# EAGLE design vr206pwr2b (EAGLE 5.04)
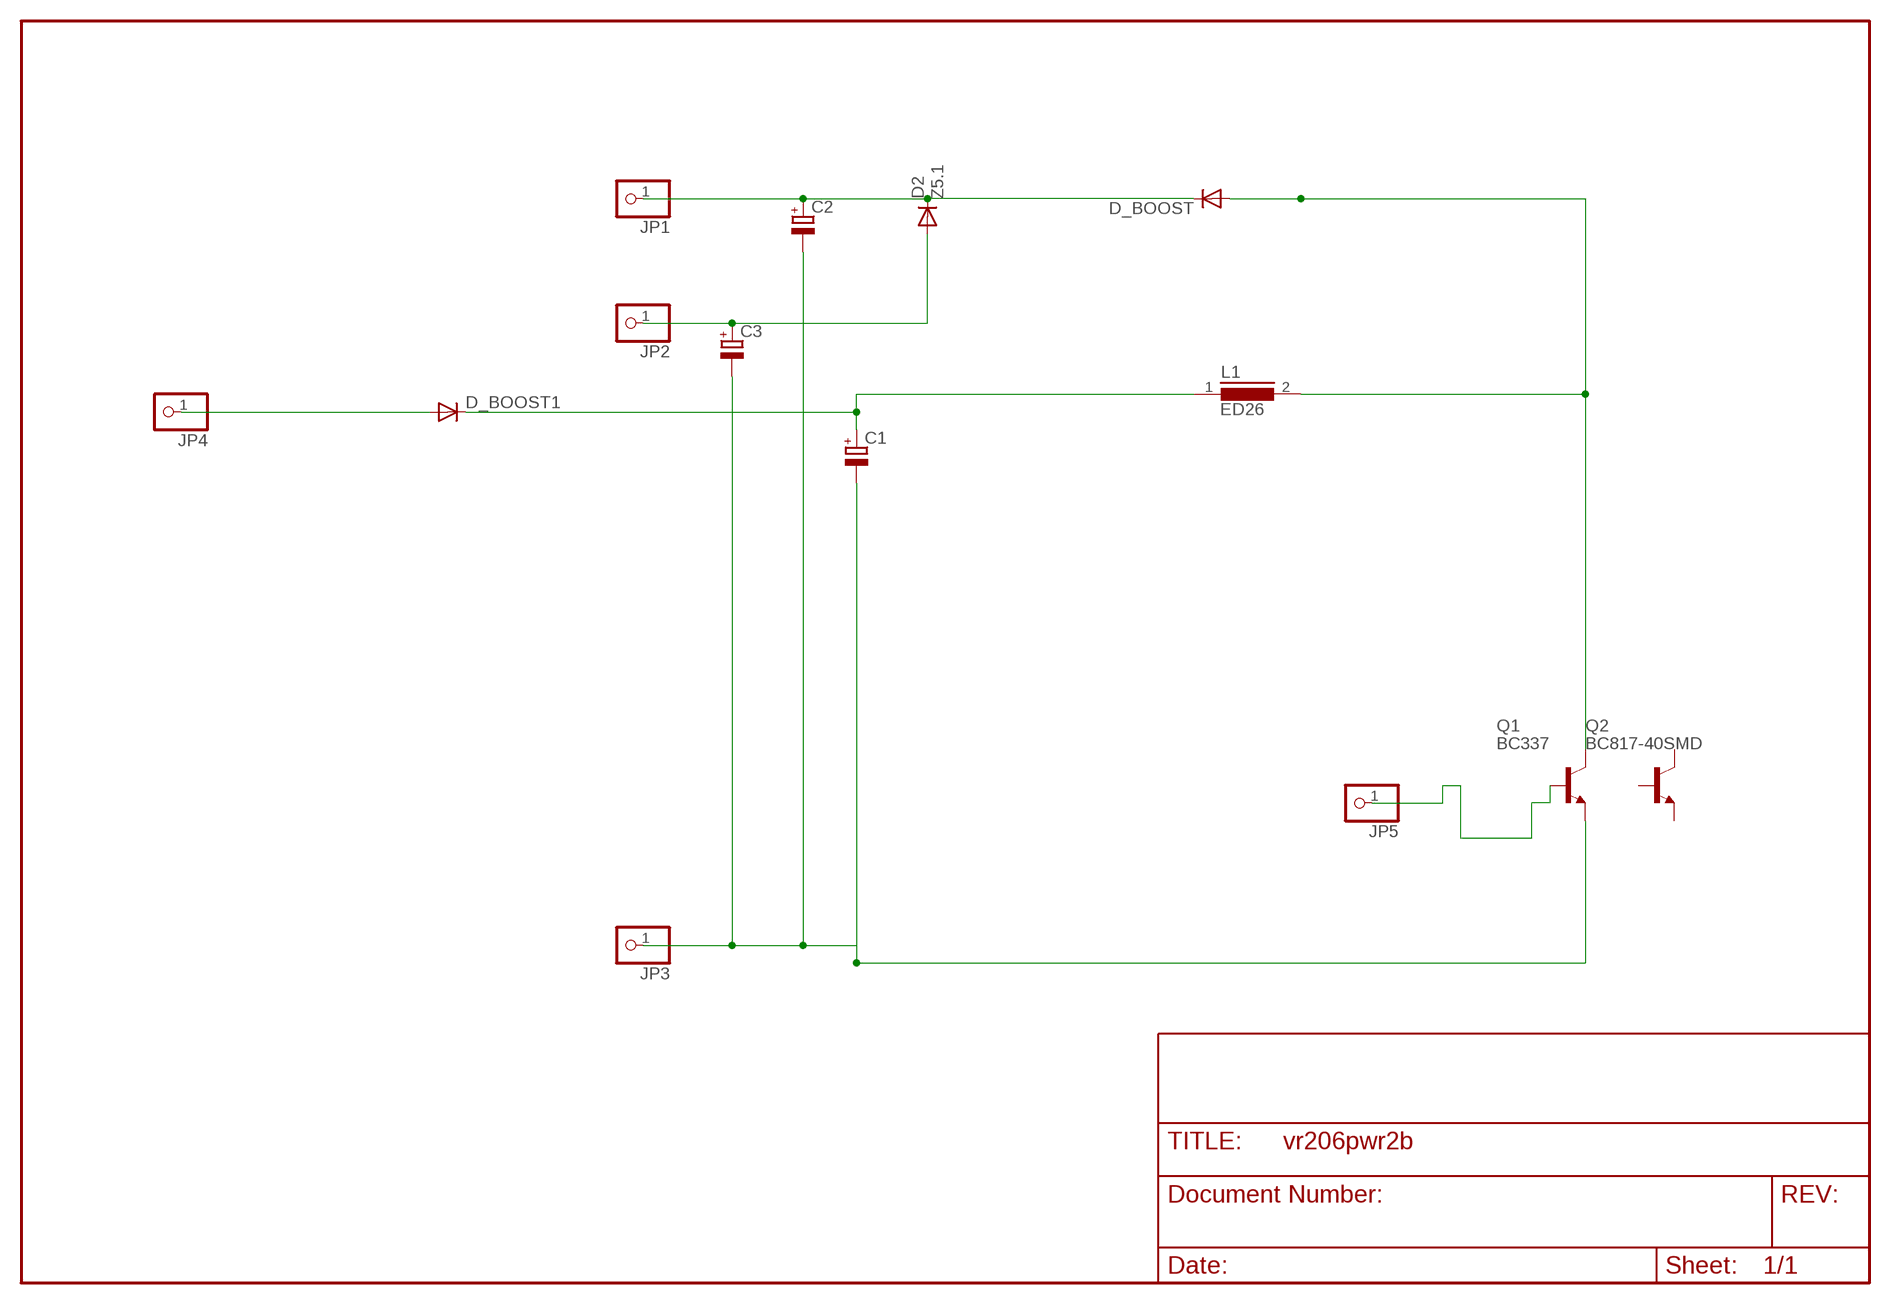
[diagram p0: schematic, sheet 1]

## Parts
C1  CPOL-EUE2.5-7  [E2,5-7]
C2  CPOL-EUE2.5-7  [E2,5-7]
C3  CPOL-EUE2-4  [E2-4]
D2  Z5.1  DIODE-D-2.5  [D-2.5]
D_BOOST  DIODE-D-10  [D-10]
D_BOOST1  DIODE-D-10  [D-10]
JP1  PINHD-1X1  [1X01]
JP2  PINHD-1X1  [1X01]
JP3  PINHD-1X1  [1X01]
JP4  PINHD-1X1  [1X01]
JP5  PINHD-1X1  [1X01]
L1  ED26  [ED26]
Q1  BC337  [TO92]
Q2  BC817-40SMD  [SOT23-BEC]

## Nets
GND: C1.- C2.- C3.- JP3.1 Q1.1(E)
HOTSPOT: D_BOOST.A L1.2 Q1.3(C)
LOAD: C2.+ D2.C D_BOOST.C JP1.1
N$1: JP5.1 Q1.2(B)
N$2: C1.+ D_BOOST1.C L1.1
N$3: D_BOOST1.A JP4.1
N$4: C3.+ D2.A JP2.1
Unconnected: Q2.B Q2.C Q2.E

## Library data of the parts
C1-C3 = rcl(2):CPOL-EU: POLARIZED CAPACITOR, European symbol
D2 D_BOOST D_BOOST1 = diode:DIODE-: DIODE
JP1-JP5 = pinhead:PINHD-1X1: PIN HEADER
L1 = inductors:ED26: INDUCTOR
Q1 = transistor-npn:BC337*: NPN Transistor
Q2 = transistor-npn:BC817*: NPN Transistor

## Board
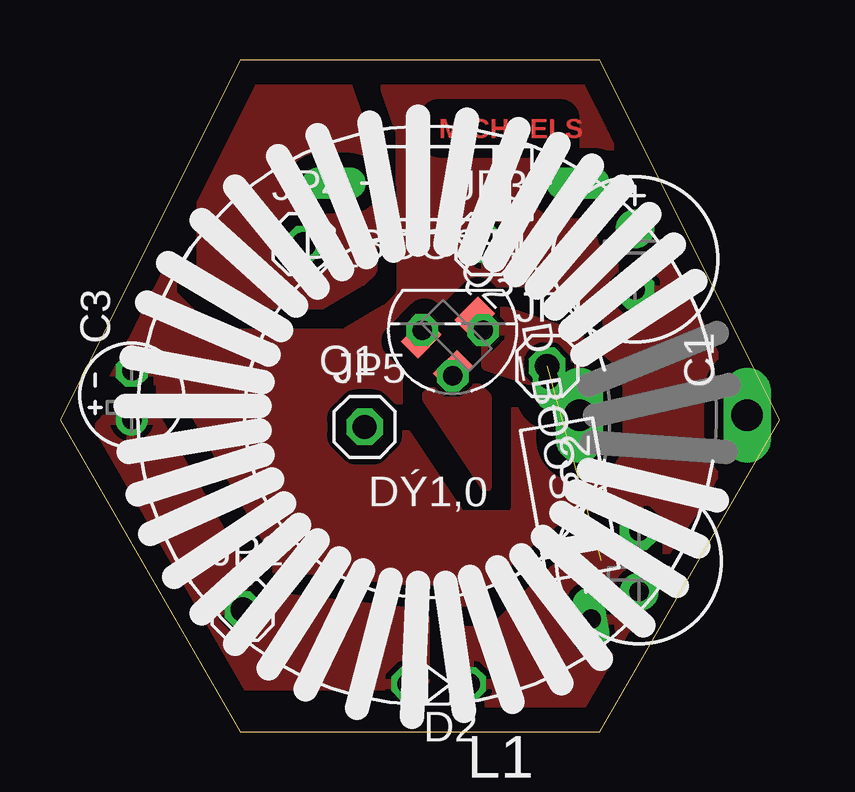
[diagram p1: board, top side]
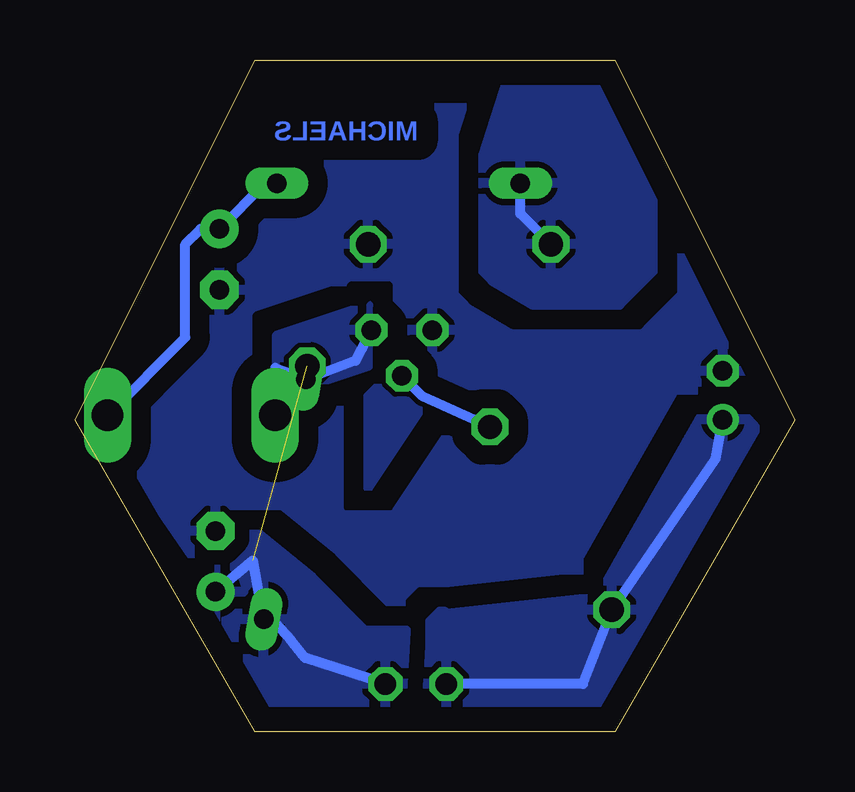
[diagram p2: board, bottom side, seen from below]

Size 30 x 28 mm. Coordinates in mm from the lower left corner, seen from the top.
Outline: 7.5,0 22.5,0 30,12.99 22.5,28 7.5,28 0,12.99 7.5,0
Copper layers (1*16): Top 0.035mm / dielectric 1.5mm / Bottom 0.035mm
Design rules "default": minimum track width 10mil, minimum drill 24mil, track to track 8mil, track to pad 8mil, pad to pad 8mil, via to via 8mil, smd to smd 8mil, copper to edge 40mil, drill to drill 8mil, minimum pad ring 10mil, minimum via ring 8mil, stop-mask expansion 4mil, vias tented up to drill 0mil, thermal gap 10mil

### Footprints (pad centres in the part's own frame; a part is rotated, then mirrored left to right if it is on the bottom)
E2,5-7 = drill 0.813 pad 1.6 round: + -1.27,0 | drill 0.813 pad 1.6 octagon: - 1.27,0
E2-4 = drill 0.813 pad 1.27 round: + -1.016,0 | drill 0.813 pad 1.27 octagon: - 1.016,0
D-2.5 = drill 0.9 octagon: A 1.27,0; C -1.27,0
D-10 = drill 0.813 long: A 5.08,0; C -5.08,0
1X01 = drill 1.016 octagon: 1 0,0
ED26 = drill 1.321 long: 1 -13.335,0; 2 -6.35,0
TO92 = drill 0.813 octagon: 1 1.27,0; 2 0,1.905; 3 -1.27,0
SOT23-BEC = smd 1 x 1.4: B -0.95,-1.1; C 0,1.1; E 0.95,-1.1

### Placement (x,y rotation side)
C1  23.98,19.68 270 top
C2  24.14,7.09 90 top
C3  2.99,14.02 90 top
D2  15.79,1.98 180 top
D_BOOST  21.25,9.68 100 top
D_BOOST1  16.51,22.86 180 top
JP1  20.32,15.24 0 top
JP2  7.62,5.08 0 top
JP3  17.78,20.32 0 top
JP4  10.16,20.32 0 top
JP5  12.7,12.7 0 top
L1  15.31,13.19 180 top
Q1  16.37,16.74 180 top
Q2  16.51,16.51 315 top

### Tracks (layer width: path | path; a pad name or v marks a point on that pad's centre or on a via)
GND
  pour Bottom (isolate 0.813, rank 3): 0.9,15.5 7.5,25.98 22.5,25.98 30.2,14.7 23.8,5.4 9.1,4.7 4.1,13.4
  pour Top (isolate 0.813, rank 3): 0.9,15.5 7.5,28 22.5,28 30.2,14.7 23.8,5.4 9.1,4.7 4.1,13.4
HOTSPOT
  Bottom 0.406: Q1.3 18.29,15.47 D_BOOST.A 21.66,15.16 L1.2
  pour Top: 17.78,17.78 21.59,16.51 21.59,13.97 17.78,15.24
  pour Bottom: 17.78,17.78 21.59,16.51 21.59,13.97 17.78,15.24
LOAD  (1 unrouted)
  Bottom 0.406: C2.+ 22.58,7.13 D_BOOST.C 22.1,5.02 21,3.8 20.4,3.07 D2.C
  pour Bottom (isolate 0.61): 16.2,4.2 17.9,4.2 20.1,6.4 22.3,8.2 23.2,8.2 24,7.4 24,3.9 23.6,3.5 23.5,3.5 22.1,0.5 16.4,0.5
  pour Top (isolate 0.61): 16.3,4.2 18,4.2 20.2,6.4 22.4,8.2 23.3,8.2 24.1,7.4 24.1,3.9 23.7,3.5 23.6,3.5 22.2,0.4 16.5,0.4
N$1
  Bottom 0.406: JP5.1 15.51,13.97 Q1.2
N$2
  Bottom 0.406: D_BOOST1.C 22.07,22.86 C1.+ 24.77,20.95 25.4,20.32 25.4,16.43 L1.1
  pour Top (isolate 0.61): 10.9,17.8 7.3,17.8 5.9,19.2 5.9,24.8 6.8,27.7 11.7,27.7 13,24 13,19.2 12.6,18.8
N$3
  Bottom 0.406: D_BOOST1.A 11.43,21.59 JP4.1
  pour Bottom (isolate 0.61): 10.9,17.8 7.3,17.8 5.9,19.2 5.9,24.8 6.9,27.7 11.8,27.7 13,24 13,19.2 12.6,18.8
N$4
  Bottom 0.406: D2.A 8.82,1.98 JP2.1 3.29,11.38 C3.+
  pour Bottom (isolate 0.61, rank 2): 14.6,5 14.8,5 15.2,4.6 15.4,1.6 15.6,0 7.9,0.3 1.4,12.4 2.3,13.4 3.8,13.3 8.2,5.6 14.5,4.9
  pour Top (isolate 0.61, rank 2): 14.6,5.1 14.8,5.1 15.2,4.7 15.2,2.1 15,1.9 7.4,1.9 1.4,12.5 2.3,13.5 3.8,13.4 8.2,5.7 14.5,5
N$5
  pour Bottom: 16.51,15.24 17.78,13.97 17.78,10.16 15.24,13.97
  pour Top: 16.51,15.24 17.78,13.97 17.78,10.16 15.24,13.97

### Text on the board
Top: MICHAELS
Bottom: MICHAELS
